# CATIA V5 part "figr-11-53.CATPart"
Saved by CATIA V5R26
Part number: Part1
Bounding box of the stored display mesh (mm): x -70 to 82, y -90 to 90, z 0 to 84
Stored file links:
  D:\_Deepak\CATIA\CATIA V5 2015 Parts Files\Part files\Partfiles\c11_catia_v5_6r2015_prt\figr-11-53.CATPart
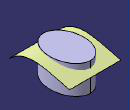
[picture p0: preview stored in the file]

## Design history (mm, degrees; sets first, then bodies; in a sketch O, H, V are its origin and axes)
Set1
  Extrude1: Element1 Sketch2, Lim1 82, Lim2 70, Direction yz-plane
Body1 (main body)
  Sketch1 on xy-plane, origin (0, 0, 0), H (1, 0, 0), V (0, 1, 0)
    ellipse A1 centre (0, 0) semi-axes 70, 50 rotation 90
    point P1 (50, 0)
    coincidence: P1 H, A1 P1
  Pad1: profile Sketch1, direction (0, 0, 1), length 84
  Sketch2 on yz-plane, origin (0, 0, 0), H (0, 1, 0), V (0, 0, 1)
    spline S1 through (-90, 50) (-30, 80) (50, 70) (90, 60)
